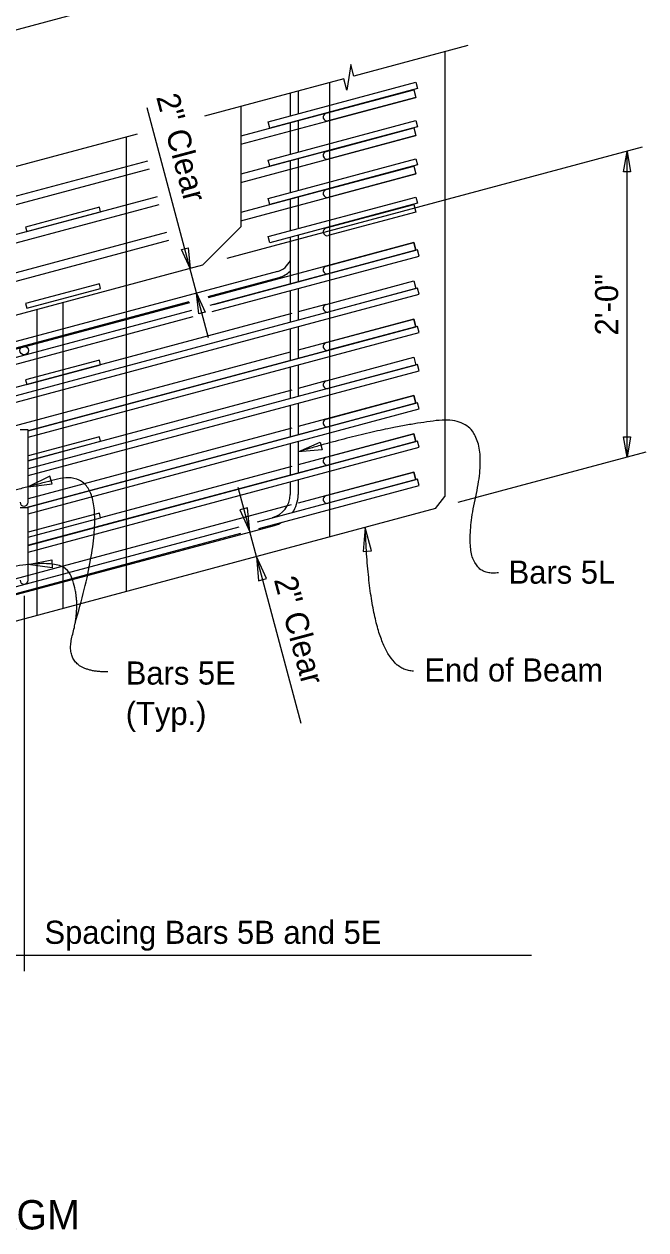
# Model space of a CAD drawing. Extents: x 120658.6 to 120712.1, y 120647.1 to 120669.9.
# Drawn here: x 120684.34 to 120688.41, y 120650.99 to 120658.88 of the extents above; entities that cross this region are included whole.
import ezdxf

# ---------------------------------------------------------------- set-up
doc = ezdxf.new("R2010")
doc.units = 0
for name, color, linetype in [('BeamConc', 7, 'Continuous'), ('BeamConc_h', 7, 'Continuous'), ('Dimension', 7, 'Continuous'), ('Miscellaneous', 7, 'Continuous'), ('Rebar', 7, 'Continuous'), ('Rebar_h', 7, 'Continuous'), ('TextStructures', 7, 'Continuous')]:
    doc.layers.add(name, color=color, linetype=linetype)

msp = doc.modelspace()

# ---------------------------------------------------------------- linework, layer by layer
at = {"layer": 'BeamConc'}
for p, q in [((120687.0908, 120658.6979), (120687.0908, 120655.789)), ((120685.7575, 120658.3406), (120685.7575, 120657.5522)), ((120685.7575, 120657.5522), (120685.5075, 120657.3022)), ((120685.5075, 120657.3022), (120684.2487, 120656.9649)), ((120687.0305, 120655.7103), (120687.0908, 120655.789)), ((120687.0305, 120655.7103), (120679.2355, 120653.6216))]:
    msp.add_line(p, q, dxfattribs=at)
at = {"layer": 'BeamConc_h'}
for p, q in [((120686.3408, 120655.5255), (120686.3408, 120658.4969)), ((120685.0075, 120658.1397), (120685.0075, 120655.1682))]:
    msp.add_line(p, q, dxfattribs=at)
at = {"layer": 'Dimension'}
for p, q in [((120685.5472, 120656.8272), (120685.1446, 120658.3299)), ((120688.3833, 120658.0728), (120685.6665, 120657.3448)), ((120688.2831, 120656.0459), (120688.2831, 120658.0459)), ((120685.4989, 120657.2999), (120685.4989, 120657.2999)), ((120685.542, 120657.1389), (120685.542, 120657.1389)), ((120688.4066, 120656.079), (120687.1777, 120655.7497)), ((120685.7381, 120655.8496), (120685.8164, 120655.5575)), ((120685.8595, 120655.3965), (120685.8164, 120655.5575)), ((120685.8894, 120655.5771), (120685.8894, 120655.5771)), ((120686.1521, 120654.3046), (120685.8595, 120655.3965)), ((120685.7865, 120655.3769), (120685.7865, 120655.3769)), ((120684.3408, 120655.1401), (120684.3408, 120652.6851)), ((120687.6582, 120652.7893), (120681.0075, 120652.7893))]:
    msp.add_line(p, q, dxfattribs=at)
for points in [[(120684.7814, 120658.9716), (120682.7067, 120658.4158), (120682.6867, 120658.4906), (120682.6742, 120658.4071), (120682.6615, 120658.3234), (120682.6415, 120658.3983), (120680.6202, 120657.8569)], [(120687.2421, 120658.7384), (120686.4964, 120658.5386), (120686.4764, 120658.6134), (120686.4639, 120658.5299), (120686.4512, 120658.4463), (120686.4312, 120658.5211), (120685.5207, 120658.2772)], [(120685.0801, 120658.1592), (120682.7067, 120657.5235), (120682.6867, 120657.5983), (120682.6742, 120657.5147), (120682.6615, 120657.4311), (120682.6415, 120657.506), (120680.6202, 120656.9646)]]:
    msp.add_lwpolyline(points, dxfattribs=at)
for points in [[(120688.2831, 120658.0458), (120688.3052, 120657.912), (120688.261, 120657.912)], [(120685.4258, 120657.2802), (120685.3698, 120657.4036), (120685.4125, 120657.4151)], [(120685.469, 120657.1192), (120685.525, 120656.9957), (120685.4823, 120656.9843)], [(120688.2831, 120656.0458), (120688.261, 120656.1795), (120688.3052, 120656.1795)], [(120686.1325, 120656.0815), (120686.2775, 120656.1454), (120686.2904, 120656.094)], [(120684.3669, 120655.853), (120684.5241, 120655.8722), (120684.509, 120655.923)], [(120685.8164, 120655.5575), (120685.8015, 120655.7152), (120685.7504, 120655.7015)], [(120686.5717, 120655.5873), (120686.5588, 120655.4295), (120686.6115, 120655.434)], [(120685.8595, 120655.3965), (120685.8744, 120655.2388), (120685.9255, 120655.2525)], [(120684.3669, 120655.3447), (120684.5222, 120655.3757), (120684.5238, 120655.3228)]]:
    msp.add_lwpolyline(points, close=True, dxfattribs=at)
for points in [[(120687.4431, 120655.291), (120687.1746, 120655.2514), (120687.4148, 120656.331), (120686.6687, 120656.2412), (120686.1325, 120656.0815)], [(120684.674, 120654.958), (120684.9813, 120656.0099), (120684.1308, 120655.7941), (120683.7002, 120655.6659)], [(120686.886, 120654.6482), (120686.6055, 120654.6482), (120686.5717, 120655.5874)], [(120684.8882, 120654.6422), (120684.5913, 120654.6422), (120684.722, 120655.1213), (120684.5544, 120655.4544), (120683.7002, 120655.1801)]]:
    msp.add_open_spline(points, degree=2, dxfattribs=at)
at = {"layer": 'Miscellaneous'}
for p, q in [((120684.5939, 120657.0574), (120684.5939, 120655.0574)), ((120684.4272, 120655.0127), (120684.4272, 120657.0127))]:
    msp.add_line(p, q, dxfattribs=at)
at = {"layer": 'Rebar'}
for p, q in [((120685.9366, 120658.2387), (120686.9026, 120658.4975)), ((120686.9134, 120658.4572), (120685.9474, 120658.1984)), ((120686.9026, 120658.4975), (120686.9134, 120658.4572)), ((120686.0804, 120658.4271), (120686.0804, 120658.2772)), ((120686.1325, 120658.4411), (120686.1325, 120658.2912)), ((120686.3157, 120658.2957), (120686.8895, 120658.4495)), ((120686.9029, 120658.3992), (120686.3292, 120658.2454)), ((120686.8895, 120658.4495), (120686.9029, 120658.3992)), ((120685.9366, 120657.9887), (120686.9026, 120658.2475)), ((120685.9474, 120658.1984), (120685.9366, 120658.2387)), ((120686.0804, 120658.234), (120686.0804, 120658.0272)), ((120686.1325, 120658.248), (120686.1325, 120658.0412)), ((120686.9026, 120658.2475), (120686.9134, 120658.2072)), ((120686.9134, 120658.2072), (120685.9474, 120657.9484)), ((120686.3157, 120658.0457), (120686.8895, 120658.1995)), ((120686.9029, 120658.1492), (120686.3292, 120657.9954)), ((120686.8895, 120658.1995), (120686.9029, 120658.1492)), ((120685.9366, 120657.7387), (120686.9026, 120657.9975)), ((120685.9474, 120657.9484), (120685.9366, 120657.9887)), ((120686.0804, 120657.984), (120686.0804, 120657.7772)), ((120686.1325, 120657.998), (120686.1325, 120657.7912)), ((120686.9026, 120657.9975), (120686.9134, 120657.9572)), ((120686.9134, 120657.9572), (120685.9474, 120657.6984)), ((120686.3157, 120657.7957), (120686.8895, 120657.9495)), ((120686.8895, 120657.9495), (120686.9029, 120657.8992)), ((120686.9029, 120657.8992), (120686.3292, 120657.7454)), ((120685.9366, 120657.4887), (120686.9026, 120657.7475)), ((120686.1325, 120657.748), (120686.1325, 120657.5412)), ((120686.9026, 120657.7475), (120686.9134, 120657.7072)), ((120685.9474, 120657.6984), (120685.9366, 120657.7387)), ((120686.9134, 120657.7072), (120685.9474, 120657.4484)), ((120686.0804, 120657.734), (120686.0804, 120657.5272)), ((120686.3157, 120657.5457), (120686.8895, 120657.6995)), ((120686.8895, 120657.6995), (120686.9029, 120657.6492)), ((120686.9029, 120657.6492), (120686.3292, 120657.4954)), ((120685.9474, 120657.4484), (120685.9366, 120657.4887)), ((120686.0804, 120657.484), (120686.0804, 120657.1787)), ((120686.1325, 120657.498), (120686.1325, 120657.1928)), ((120686.3157, 120657.2957), (120686.8895, 120657.4495)), ((120686.8895, 120657.4495), (120686.9029, 120657.3992)), ((120686.9134, 120657.4019), (120685.5556, 120657.0381)), ((120685.5706, 120656.999), (120686.9242, 120657.3617)), ((120686.9029, 120657.3992), (120686.3292, 120657.2454)), ((120686.9242, 120657.3617), (120686.9134, 120657.4019)), ((120685.9982, 120657.2611), (120681.6743, 120656.1025)), ((120685.5433, 120657.0976), (120686.009, 120657.2223)), ((120686.3157, 120657.0457), (120686.8895, 120657.1995)), ((120686.8895, 120657.1995), (120686.9029, 120657.1492)), ((120686.9134, 120657.1519), (120678.4242, 120654.8772)), ((120686.0804, 120657.1356), (120686.0804, 120656.9287)), ((120686.1325, 120657.1496), (120686.1325, 120656.9427)), ((120686.9029, 120657.1492), (120686.3292, 120656.9954)), ((120686.9242, 120657.1117), (120686.9134, 120657.1519)), ((120678.435, 120654.837), (120686.9242, 120657.1117)), ((120681.6668, 120656.0588), (120685.4194, 120657.0644)), ((120685.4351, 120657.0058), (120678.4242, 120655.1272)), ((120678.435, 120655.087), (120685.4459, 120656.9656)), ((120686.9134, 120656.9019), (120684.3669, 120656.2196)), ((120686.0804, 120656.8856), (120686.0804, 120656.6787)), ((120686.1325, 120656.8996), (120686.1325, 120656.6927)), ((120686.3157, 120656.7957), (120686.8895, 120656.9495)), ((120686.9029, 120656.8992), (120686.3292, 120656.7454)), ((120686.8895, 120656.9495), (120686.9029, 120656.8992)), ((120686.9242, 120656.8617), (120686.9134, 120656.9019)), ((120684.3669, 120656.1765), (120686.9242, 120656.8617)), ((120686.9134, 120656.6519), (120684.3669, 120655.9696)), ((120686.1325, 120656.6496), (120686.1325, 120656.4427)), ((120686.3157, 120656.5457), (120686.8895, 120656.6995)), ((120686.9029, 120656.6492), (120686.3292, 120656.4954)), ((120686.8895, 120656.6995), (120686.9029, 120656.6492)), ((120686.9242, 120656.6117), (120686.9134, 120656.6519)), ((120684.3669, 120655.9265), (120686.9242, 120656.6117)), ((120686.0804, 120656.6356), (120686.0804, 120656.4287)), ((120686.3157, 120656.2957), (120686.8895, 120656.4495)), ((120686.8895, 120656.4495), (120686.9029, 120656.3992)), ((120686.9134, 120656.4019), (120684.3523, 120655.7157)), ((120684.3669, 120655.6765), (120686.9242, 120656.3617)), ((120686.0804, 120656.3856), (120686.0804, 120656.1787)), ((120686.1325, 120656.3996), (120686.1325, 120656.1927)), ((120686.9029, 120656.3992), (120686.3292, 120656.2454)), ((120686.9242, 120656.3617), (120686.9134, 120656.4019)), ((120684.3669, 120656.2257), (120684.3148, 120656.2257)), ((120684.3669, 120655.7517), (120684.3669, 120656.2257)), ((120686.3157, 120656.0457), (120686.8895, 120656.1995)), ((120686.8895, 120656.1995), (120686.9029, 120656.1492)), ((120684.3669, 120655.4265), (120686.9242, 120656.1117)), ((120686.9134, 120656.1519), (120684.3696, 120655.4703)), ((120686.0804, 120656.1356), (120686.0804, 120655.9287)), ((120686.1325, 120656.1496), (120686.1325, 120655.9427)), ((120686.9029, 120656.1492), (120686.3292, 120655.9954)), ((120686.9242, 120656.1117), (120686.9134, 120656.1519)), ((120686.3157, 120655.7957), (120686.8895, 120655.9495)), ((120686.8895, 120655.9495), (120686.9029, 120655.8992)), ((120686.9134, 120655.9019), (120685.8656, 120655.6212)), ((120685.8766, 120655.581), (120686.9242, 120655.8617)), ((120686.0804, 120655.8856), (120686.0804, 120655.8021)), ((120686.1325, 120655.8996), (120686.1325, 120655.8021)), ((120686.9029, 120655.8992), (120686.3292, 120655.7454)), ((120686.9242, 120655.8617), (120686.9134, 120655.9019)), ((120684.3669, 120655.7157), (120684.3148, 120655.7157)), ((120684.3669, 120655.2417), (120684.3669, 120655.7157)), ((120685.7448, 120655.5888), (120678.4242, 120653.6272)), ((120678.435, 120653.587), (120685.7573, 120655.549)), ((120679.4781, 120653.8592), (120685.9781, 120655.6009))]:
    msp.add_line(p, q, dxfattribs=at)
for points in [[(120684.3579, 120657.5211), (120684.8408, 120657.6505), (120684.8327, 120657.6807), (120684.3498, 120657.5513)], [(120684.3579, 120657.0211), (120684.8408, 120657.1505), (120684.8327, 120657.1807), (120684.3498, 120657.0513)], [(120684.3579, 120656.5211), (120684.8408, 120656.6505), (120684.8327, 120656.6807), (120684.3498, 120656.5513)]]:
    msp.add_lwpolyline(points, close=True, dxfattribs=at)
for points in [[(120684.3669, 120656.0235), (120684.8408, 120656.1505), (120684.8327, 120656.1807), (120684.3669, 120656.0559)], [(120684.3669, 120655.5235), (120684.8408, 120655.6505), (120684.8327, 120655.6807), (120684.3669, 120655.5559)]]:
    msp.add_lwpolyline(points, dxfattribs=at)
msp.add_circle((120684.3408, 120656.7442), 0.0287, dxfattribs=at)
for centre, radius, start, end in [((120686.3225, 120658.2706), 0.026, 105, 285), ((120686.3225, 120658.0206), 0.026, 105, 285), ((120686.3225, 120657.7706), 0.026, 105, 285), ((120686.3225, 120657.5206), 0.026, 105, 285), ((120685.9658, 120657.3819), 0.125, 285, 336.44353), ((120686.3225, 120657.2706), 0.026, 105, 285), ((120685.9658, 120657.3833), 0.1667, 285, 313.43746), ((120686.3225, 120657.0206), 0.026, 105, 285), ((120686.3225, 120656.7706), 0.026, 105, 285), ((120686.3225, 120656.5206), 0.026, 105, 285), ((120686.3225, 120656.2706), 0.026, 105, 285), ((120686.3225, 120656.0206), 0.026, 105, 285), ((120685.9242, 120655.8021), 0.1562, 285, 360), ((120685.9242, 120655.8021), 0.2083, 324.99028, 360), ((120686.3225, 120655.7706), 0.026, 105, 285), ((120684.3408, 120655.7517), 0.026, 179.99982, 359.99949), ((120685.9242, 120655.8021), 0.2083, 285, 299.93885), ((120684.3408, 120655.2417), 0.026, 179.99982, 359.99949)]:
    msp.add_arc(centre, radius, start, end, dxfattribs=at)
at = {"layer": 'Rebar_h'}
for p, q in [((120686.8895, 120658.4494), (120685.7575, 120658.1461)), ((120685.7575, 120658.0923), (120686.9029, 120658.3992)), ((120686.8895, 120658.1994), (120685.7575, 120657.8961)), ((120685.7575, 120657.8423), (120686.9029, 120658.1492)), ((120685.1478, 120657.9828), (120679.411, 120656.4456)), ((120679.0228, 120656.2877), (120685.1613, 120657.9325)), ((120686.8895, 120657.9494), (120685.7575, 120657.6461)), ((120685.7575, 120657.5923), (120686.9029, 120657.8992)), ((120685.2103, 120657.7495), (120679.411, 120656.1956)), ((120679.0228, 120656.0377), (120685.2238, 120657.6993)), ((120685.2728, 120657.5163), (120679.411, 120655.9456)), ((120679.0228, 120655.7877), (120685.2863, 120657.466)), ((120686.8895, 120657.4494), (120685.5435, 120657.0888)), ((120686.9029, 120657.3992), (120686.8895, 120657.4494)), ((120685.5816, 120657.0451), (120686.9029, 120657.3992)), ((120685.4216, 120657.0561), (120678.4356, 120655.1842)), ((120686.8895, 120655.9494), (120686.1325, 120655.7466)), ((120686.9029, 120655.8992), (120686.8895, 120655.9494)), ((120686.086, 120655.7341), (120683.7002, 120655.0949))]:
    msp.add_line(p, q, dxfattribs=at)
for points in [[(120686.3145, 120657.0454), (120686.1325, 120656.9966)], [(120686.0908, 120656.9854), (120679.2575, 120655.1545)], [(120684.3669, 120656.2197), (120686.9029, 120656.8992), (120686.8895, 120656.9494), (120686.1325, 120656.7466)], [(120686.0804, 120656.7327), (120679.2575, 120654.9045)], [(120686.0908, 120656.4854), (120684.3669, 120656.0235)], [(120686.3157, 120656.5457), (120686.1325, 120656.4966)], [(120684.3669, 120655.7197), (120686.9029, 120656.3992), (120686.8895, 120656.4494), (120686.1325, 120656.2466)], [(120686.0908, 120656.2354), (120684.3669, 120655.7735)], [(120684.3669, 120655.4697), (120686.9029, 120656.1492), (120686.8895, 120656.1994), (120686.1325, 120655.9966)], [(120686.0908, 120655.9854), (120684.8408, 120655.6505)]]:
    msp.add_lwpolyline(points, dxfattribs=at)

# ---------------------------------------------------------------- texts
at = {"layer": 'Dimension'}
for s, height, p in [('Bars 5E ', 0.1512, (120685.0055, 120654.5598)), ('(Typ.)', 0.1512, (120685.0055, 120654.2958)), ('TOP VIEW OF SKEWED END DIAPHRAGM', 0.192, (120679.5977, 120650.9973))]:
    msp.add_text(s, height=height, dxfattribs=at).set_placement(p)
at = {"layer": 'TextStructures'}
for s, rotation, p in [('2" Clear', 285, (120685.2035, 120658.4019)), ('2\'-0"', 90, (120688.2253, 120656.8422)), ('2" Clear', 285, (120685.9732, 120655.2463))]:
    msp.add_text(s, height=0.1512, rotation=rotation, dxfattribs=at).set_placement(p)
for s, p in [('Bars 5L', (120687.5089, 120655.2197)), ('End of Beam', (120686.958, 120654.5798)), ('Spacing Bars 5B and 5E', (120684.4741, 120652.8647))]:
    msp.add_text(s, height=0.1512, dxfattribs=at).set_placement(p)

doc.saveas('drawing.dxf')
